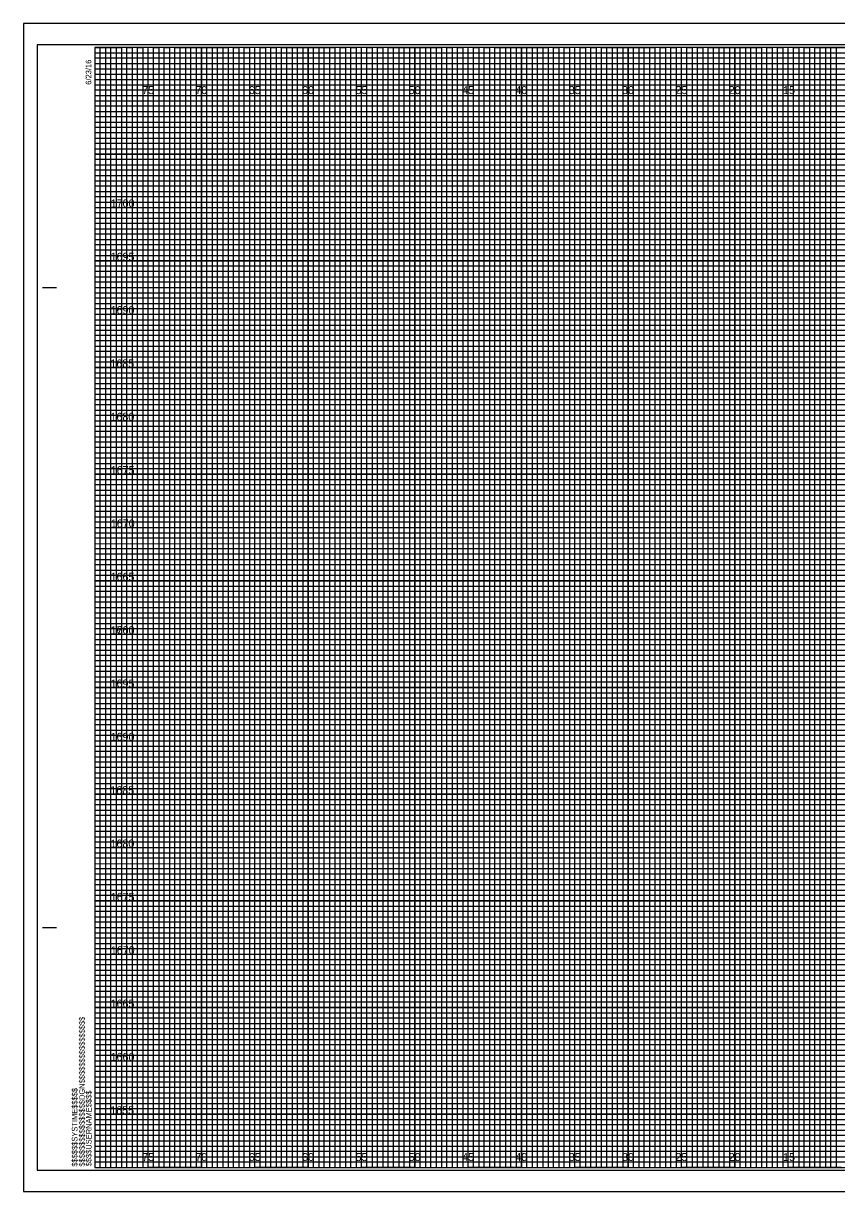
# Model space of a CAD drawing. Extents: x -7 to 162, y -2 to 217.
# Drawn here: x -6.7 to 69.5, y -2.3 to 107.3 of the extents above; entities that cross this region are included whole.
import ezdxf

# ---------------------------------------------------------------- set-up
doc = ezdxf.new("R2010")
doc.units = 0
for name, color, linetype in [('Raster_Level_0', 7, 'Continuous'), ('Scratch_Level_3', 7, 'Continuous'), ('Sheet Cross Section CELL', 7, 'Continuous'), ('Sheet Cross Section Grid Major CELL', 7, 'Continuous'), ('Sheet Cross Section Grid Middle CELL', 7, 'Continuous'), ('Sheet Cross Section Grid Minor 1 CELL', 7, 'Continuous'), ('Sheet Cross Section Grid Minor 2 CELL', 7, 'Continuous'), ('Sheet Cutting Line CELL', 7, 'Continuous'), ('Sheet DOT Grid CELL', 7, 'Continuous'), ('Sheet Plot Border Inside CELL', 7, 'Continuous'), ('Sheet Plot Border Outside CELL', 7, 'Continuous')]:
    doc.layers.add(name, color=color, linetype=linetype)

msp = doc.modelspace()

# ---------------------------------------------------------------- linework, layer by layer
at = {"layer": 'Sheet Cross Section CELL'}
for p, q in [((-4.9, 82.5), (-3.65, 82.5)), ((-4.85, 82.5), (-3.6, 82.5)), ((-4.9, 22.5), (-3.65, 22.5)), ((-4.85, 22.5), (-3.6, 22.5)), ((0, 0), (0, 0)), ((0, 0), (0, 0)), ((0, 0), (0, 0)), ((0, 0), (0, 0)), ((0, 0), (0, 0)), ((0, 0), (0, 0)), ((0, 0), (0, 0))]:
    msp.add_line(p, q, dxfattribs=at)
msp.add_lwpolyline([(160, 105), (0, 105), (0, 0), (160, 0)], close=True, dxfattribs=at)
at = {"layer": 'Sheet Cross Section Grid Major CELL'}
for p, q in [((5, 105), (0, 105)), ((5, 0), (5, 105)), ((15, 105), (10, 105)), ((10, 105), (10, 0)), ((15, 0), (15, 105)), ((25, 105), (20, 105)), ((20, 105), (20, 0)), ((25, 0), (25, 105)), ((35, 105), (30, 105)), ((30, 105), (30, 0)), ((35, 0), (35, 105)), ((45, 105), (40, 105)), ((40, 105), (40, 0)), ((45, 0), (45, 105)), ((55, 105), (50, 105)), ((50, 105), (50, 0)), ((55, 0), (55, 105)), ((65, 105), (60, 105)), ((60, 105), (60, 0)), ((65, 0), (65, 105)), ((10, 0), (5, 0)), ((20, 0), (15, 0)), ((30, 0), (25, 0)), ((40, 0), (35, 0)), ((50, 0), (45, 0)), ((60, 0), (55, 0)), ((70, 0), (65, 0))]:
    msp.add_line(p, q, dxfattribs=at)
for points in [[(0, 100), (160, 100), (160, 95), (0, 95)], [(0, 90), (160, 90), (160, 85), (0, 85)], [(0, 80), (160, 80), (160, 75), (0, 75)], [(0, 70), (160, 70), (160, 65), (0, 65)], [(0, 60), (160, 60), (160, 55), (0, 55)], [(0, 50), (160, 50), (160, 45), (0, 45)], [(0, 40), (160, 40), (160, 35), (0, 35)], [(0, 30), (160, 30), (160, 25), (0, 25)], [(0, 20), (160, 20), (160, 15), (0, 15)], [(0, 10), (160, 10), (160, 5), (0, 5)]]:
    msp.add_lwpolyline(points, dxfattribs=at)
at = {"layer": 'Sheet Cross Section Grid Middle CELL'}
for points in [[(0, 105), (2.5, 105), (2.5, 0), (7.5, 0), (7.5, 105), (12.5, 105), (12.5, 0), (17.5, 0), (17.5, 105), (22.5, 105), (22.5, 0), (27.5, 0), (27.5, 105), (32.5, 105), (32.5, 0), (37.5, 0), (37.5, 105), (42.5, 105), (42.5, 0), (47.5, 0), (47.5, 105), (52.5, 105), (52.5, 0), (57.5, 0), (57.5, 105), (62.5, 105), (62.5, 0), (67.5, 0), (67.5, 105), (72.5, 105)], [(0, 102.5), (137.5, 102.5)], [(0, 92.5), (160, 92.5), (160, 97.5), (0, 97.5)], [(0, 82.5), (160, 82.5), (160, 87.5), (0, 87.5)], [(0, 72.5), (160, 72.5), (160, 77.5), (0, 77.5)], [(0, 62.5), (160, 62.5), (160, 67.5), (0, 67.5)], [(0, 52.5), (160, 52.5), (160, 57.5), (0, 57.5)], [(0, 42.5), (160, 42.5), (160, 47.5), (0, 47.5)], [(0, 32.5), (160, 32.5), (160, 37.5), (0, 37.5)], [(0, 22.5), (160, 22.5), (160, 27.5), (0, 27.5)], [(0, 12.5), (160, 12.5), (160, 17.5), (0, 17.5)], [(0, 2.5), (160, 2.5), (160, 7.5), (0, 7.5)]]:
    msp.add_lwpolyline(points, dxfattribs=at)
at = {"layer": 'Sheet Cross Section Grid Minor 1 CELL'}
for p, q in [((0, 104.5), (130, 104.5)), ((130, 103.99), (0, 103.99)), ((0, 103.99), (0, 103.5)), ((0, 103.5), (130, 103.5)), ((130, 102.95), (0, 102.95)), ((0, 102.95), (0, 102)), ((0, 102), (160, 102))]:
    msp.add_line(p, q, dxfattribs=at)
for points in [[(0, 101.5), (135, 101.5), (160, 101.5), (160, 101), (0, 101)], [(0, 100.5), (160, 100.5), (160, 99.5), (0, 99.5)], [(0, 99), (160, 99), (160, 98.5), (0, 98.49)], [(0, 98), (160, 98), (160, 97), (0, 97)], [(0, 96.5), (160, 96.5), (160, 96), (0, 96)], [(0, 95.5), (160, 95.5), (160, 94.5), (0, 94.5)], [(0, 94), (160, 94), (160, 93.5), (0, 93.5)], [(0, 93), (160, 93), (160, 92), (0, 92)], [(0, 91.5), (160, 91.5), (160, 91), (0, 91)], [(0, 90.5), (160, 90.5), (160, 89.5), (0, 89.5)], [(0, 89), (160, 89), (160, 88.5), (0, 88.5)], [(0, 88), (160, 88), (160, 86.98), (160, 86.5), (160, 86), (0, 86)], [(0, 87), (160, 87), (160, 86.5), (0, 86.5)], [(0, 85.5), (160, 85.5), (160, 84.5), (0, 84.52)], [(0, 84.52), (160, 84.5), (160, 84), (0, 84)], [(0, 83.5), (160, 83.5), (160, 83), (0, 83)], [(0, 82), (160, 82), (160, 81.5), (0, 81.5)], [(0, 81), (160, 81), (160, 80.5), (0, 80.5)], [(-0.04, 79.45), (160, 79.45), (160, 78.94), (-0.04, 78.94)], [(0, 78.5), (160, 78.5), (160, 78), (0, 78)], [(0, 77), (160, 77), (160, 76.5), (0, 76.5)], [(0, 76), (160, 76), (160, 75.5), (0, 75.5)], [(0, 74.5), (160, 74.5), (160, 74), (0, 74)], [(0, 73.5), (160, 73.5), (160, 73), (0, 73)], [(0, 72), (160, 72), (160, 71.5), (0, 71.5)], [(0, 71), (160, 71), (160, 70.5), (0, 70.5)], [(0, 69.5), (160, 69.5), (160, 68.99), (0, 69)], [(0, 68.5), (160, 68.5), (160, 68), (0, 68)], [(0, 67), (160, 67), (160, 66.5), (0, 66.5)], [(0, 66), (160, 66), (160, 65.5), (0, 65.5)], [(0, 64.5), (160, 64.5), (160, 64), (0, 64)], [(0, 63.5), (160, 63.5), (160, 63), (0, 63)], [(0, 62), (160, 62), (160, 61.5), (0, 61.5)], [(0, 61), (160, 61), (160, 60.5), (0, 60.5)], [(0, 59.5), (160, 59.5), (160, 59), (0, 59)], [(0, 58.5), (160.03, 58.45), (160, 58), (0, 58)], [(0, 57), (160, 57), (160, 56.5), (0, 56.5)], [(0, 56), (160, 56), (160, 55.5), (0, 55.5)], [(0, 54.5), (160, 54.5), (160, 54), (0, 54)], [(0, 53.5), (160, 53.5), (160, 53), (0, 53)], [(0, 52), (160, 52), (160, 51.5), (0, 51.5)], [(0, 51), (160, 51), (160, 50.5), (0, 50.5)], [(0, 49.5), (160, 49.5), (160, 49), (0, 49)], [(0, 48.5), (160, 48.5), (160, 48), (0, 48)], [(0, 47), (160, 47), (160, 46.5), (0, 46.5)], [(0, 46), (160, 46), (160, 45.5), (0, 45.5)], [(0, 44.5), (160, 44.5), (160, 44), (0, 44)], [(0, 43.5), (160, 43.5), (160, 43), (0, 43)], [(0, 42), (160, 42), (160, 41.5), (0, 41.5)], [(0, 41), (160, 41), (160, 40.5), (0, 40.5)], [(0, 39.5), (160, 39.5), (160, 38.99), (0, 39)], [(0, 38.5), (160, 38.5), (160, 38), (0, 38)], [(0, 37), (160, 37), (160, 36.5), (0, 36.5)], [(0, 36), (160, 36), (160, 35.5), (0, 35.5)], [(0, 34.5), (160, 34.5), (160, 34), (0, 34)], [(0, 33.5), (160, 33.5), (160, 33), (0, 33)], [(0, 32), (160, 32), (160, 31.5), (0, 31.5)], [(0, 31), (160, 31), (160, 30.5), (0, 30.5)], [(0, 29.5), (160, 29.5), (160, 29), (0, 29)], [(0, 28.5), (160.03, 28.46), (160, 28), (0, 28)], [(0, 27), (160, 27), (160, 26.5), (0, 26.5)], [(0, 26), (160, 26), (160, 25.5), (0, 25.5)], [(0, 24.5), (160, 24.5), (160, 24), (0, 24)], [(0, 23.5), (160, 23.5), (160, 23), (0, 23)], [(0, 22), (160, 22), (160, 21.5), (0, 21.5)], [(0, 21), (160, 21), (160, 20.5), (0, 20.5)], [(0, 19.5), (160, 19.5), (160, 19), (0, 19)], [(0, 18.5), (160, 18.5), (160, 18), (0, 18)], [(0, 17), (160, 17), (160, 16.5), (0, 16.5)], [(0, 16), (160, 16), (160, 15.5), (0, 15.5)], [(0, 14.5), (160, 14.5), (160, 14), (0, 14)], [(0, 13.5), (160, 13.5), (160, 13), (0, 13)], [(0, 12), (160, 12), (160, 11.5), (0, 11.5)], [(0, 11), (160, 11), (160, 10.5), (0, 10.5)], [(0, 9.5), (160, 9.5), (160, 9), (0, 9)], [(0, 8.5), (160, 8.5), (160, 8), (0, 8)], [(0, 7), (160, 7), (160, 6.5), (0, 6.5)], [(0, 6), (160, 6), (160, 5.5), (0, 5.5)], [(0, 4.5), (160, 4.5), (160, 4), (0, 4)], [(0, 3.5), (160, 3.5), (160, 3), (0, 3)], [(0, 2), (160, 2), (160, 1.5), (0, 1.5)], [(0, 1), (160, 1), (160, 0.5), (0, 0.5)]]:
    msp.add_lwpolyline(points, dxfattribs=at)
at = {"layer": 'Sheet Cross Section Grid Minor 2 CELL'}
for points in [[(0, 0), (0.5, 0), (0.5, 105), (1, 105), (1, 0)], [(1, 0), (1.5, 0), (1.5, 105), (2, 105), (2, 0)], [(2.5, 0), (3, 0), (3, 105), (3.5, 105), (3.5, 0)], [(3.5, 0), (4, 0), (4, 105), (4.5, 105), (4.5, 0)], [(5, 0), (5.5, 0), (5.5, 105), (6, 105), (6, 0)], [(6, 0), (6.5, 0), (6.5, 105), (7, 105), (7, 0)], [(7.5, 0), (8, 0), (8, 105), (8.5, 105), (8.5, 0)], [(8.5, 0), (9, 0), (9, 105), (9.5, 105), (9.5, 0)], [(10, 0), (10.5, 0), (10.5, 105), (11, 105), (11, 0)], [(11, 0), (11.5, 0), (11.5, 105), (12, 105), (12, 0)], [(12.5, 0), (13, 0), (13, 105), (13.5, 105), (13.5, 0)], [(13.5, 0), (14, 0), (14, 105), (14.5, 105), (14.5, 0)], [(15, 0), (15.5, 0), (15.5, 105), (16, 105), (16, 0)], [(16, 0), (16.5, 0), (16.5, 105), (17, 105), (17, 0)], [(17.5, 0), (18, 0), (18, 105), (18.5, 105), (18.5, 0)], [(18.5, 0), (19, 0), (19, 105), (19.5, 105), (19.5, 0)], [(20, 0), (20.5, 0), (20.5, 105), (21, 105), (21, 0)], [(21, 0), (21.5, 0), (21.5, 105), (22, 105), (22, 0)], [(22.5, 0), (23, 0), (23, 105), (23.5, 105), (23.5, 0)], [(23.5, 0), (24, 0), (24, 105), (24.5, 105), (24.5, 0)], [(25, 0), (25.5, 0), (25.5, 105), (26, 105), (26, 0)], [(26, 0), (26.5, 0), (26.5, 105), (27, 105), (27, 0)], [(27.5, 0), (28, 0), (28, 105), (28.5, 105), (28.5, 0)], [(28.5, 0), (29, 0), (29, 105), (29.5, 105), (29.5, 0)], [(30, 0), (30.5, 0), (30.5, 105), (31, 105), (31, 0)], [(31, 0), (31.5, 0), (31.5, 105), (32, 105), (32, 0)], [(32.5, 0), (33, 0), (33, 105), (33.5, 105), (33.5, 0)], [(33.5, 0), (34, 0), (34, 105), (34.5, 105), (34.5, 0)], [(35, 0), (35.5, 0), (35.5, 105), (36, 105), (36, 0)], [(36, 0), (36.5, 0), (36.5, 105), (37, 105), (37, 0)], [(37.5, 0), (38, 0), (38, 105), (38.5, 105), (38.5, 0)], [(38.5, 0), (39, 0), (39, 105), (39.5, 105), (39.5, 0)], [(40, 0), (40.5, 0), (40.5, 105), (41, 105), (41, 0)], [(41, 0), (41.5, 0), (41.5, 105), (42, 105), (42, 0)], [(42.5, 0), (43, 0), (43, 105), (43.5, 105), (43.5, 0)], [(43.5, 0), (44, 0), (44, 105), (44.5, 105), (44.5, 0)], [(45, 0), (45.5, 0), (45.5, 105), (46, 105), (46, 0)], [(46, 0), (46.5, 0), (46.5, 105), (47, 105), (47, 0)], [(47.5, 0), (48, 0), (48, 105), (48.5, 105), (48.5, 0)], [(48.5, 0), (49, 0), (49, 105), (49.5, 105), (49.5, 0)], [(50, 0), (50.5, 0), (50.5, 105), (51, 105), (51, 0)], [(51, 0), (51.5, 0), (51.5, 105), (52, 105), (52, 0)], [(52.5, 0), (53, 0), (53, 105), (53.5, 105), (53.5, 0)], [(53.5, 0), (54, 0), (54, 105), (54.5, 105), (54.5, 0)], [(55, 0), (55.5, 0), (55.5, 105), (56, 105), (56, 0)], [(56, 0), (56.5, 0), (56.5, 105), (57, 105), (57, 0)], [(57.5, 0), (58, 0), (58, 105), (58.5, 105), (58.5, 0)], [(58.5, 0), (59, 0), (59, 105), (59.5, 105), (59.5, 0)], [(60, 0), (60.5, 0), (60.5, 105), (61, 105), (61, 0)], [(61, 0), (61.5, 0), (61.5, 105), (62, 105), (62, 0)], [(62.5, 0), (63, 0), (63, 105), (63.5, 105), (63.5, 0)], [(63.5, 0), (64, 0), (64, 105), (64.5, 105), (64.5, 0)], [(65, 0), (65.5, 0), (65.5, 105), (66, 105), (66, 0)], [(66, 0), (66.5, 0), (66.5, 105), (67, 105), (67, 0)], [(67.5, 0), (68, 0), (68, 105), (68.5, 105), (68.5, 0)], [(68.5, 0), (69, 0), (69, 105), (69.5, 105), (69.5, 0)]]:
    msp.add_lwpolyline(points, dxfattribs=at)
at = {"layer": 'Sheet Cutting Line CELL'}
for p, q in [((161.65, 107.25), (-6.7, 107.25)), ((-6.7, 107.25), (-6.7, -2.25)), ((-6.7, -2.25), (161.65, -2.25))]:
    msp.add_line(p, q, dxfattribs=at)
at = {"layer": 'Sheet DOT Grid CELL'}
for p, q in [((5, 0), (5, 105)), ((10, 0), (10, 105)), ((15, 0), (15, 105)), ((20, 0), (20, 105)), ((25, 0), (25, 105)), ((30, 0), (30, 105)), ((35, 0), (35, 105)), ((40, 0), (40, 105)), ((45, 0), (45, 105)), ((50, 0), (50, 105)), ((55, 0), (55, 105)), ((60, 0), (60, 105)), ((65, 0), (65, 105)), ((0, 100), (160, 100)), ((0, 95), (160, 95)), ((0, 90), (160, 90)), ((0, 85), (160, 85)), ((0, 80), (160, 80)), ((0, 75), (160, 75)), ((0, 70), (160, 70)), ((0, 65), (160, 65)), ((0, 60), (160, 60)), ((0, 55), (160, 55)), ((0, 50), (160, 50)), ((0, 45), (160, 45)), ((0, 40), (160, 40)), ((0, 35), (160, 35)), ((0, 30), (160, 30)), ((0, 25), (160, 25)), ((0, 20), (160, 20)), ((0, 15), (160, 15)), ((0, 10), (160, 10)), ((0, 5), (160, 5))]:
    msp.add_line(p, q, dxfattribs=at)
at = {"layer": 'Sheet Plot Border Inside CELL'}
msp.add_lwpolyline([(-5.4, -0.25), (161.2, -0.25), (161.2, 105.25), (-5.4, 105.25)], close=True, dxfattribs=at)
at = {"layer": 'Sheet Plot Border Outside CELL'}
msp.add_lwpolyline([(-6.7, -2.25), (161.65, -2.25), (161.65, 107.25), (-6.7, 107.25)], close=True, dxfattribs=at)

# ---------------------------------------------------------------- texts
at = {"layer": 'Raster_Level_0'}
for s, p in [('75', (4.44, 100.62)), ('70', (9.43, 100.62)), ('65', (14.44, 100.62)), ('60', (19.43, 100.62)), ('55', (24.44, 100.62)), ('50', (29.43, 100.62)), ('45', (34.44, 100.62)), ('40', (39.43, 100.62)), ('35', (44.44, 100.62)), ('30', (49.43, 100.62)), ('25', (54.44, 100.62)), ('20', (59.43, 100.62)), ('15', (64.53, 100.62)), ('75', (4.44, 0.62)), ('70', (9.43, 0.62)), ('65', (14.44, 0.62)), ('60', (19.43, 0.62)), ('55', (24.44, 0.62)), ('50', (29.43, 0.62)), ('45', (34.44, 0.62)), ('40', (39.43, 0.62)), ('35', (44.44, 0.62)), ('30', (49.43, 0.62)), ('25', (54.44, 0.62)), ('20', (59.43, 0.62)), ('15', (64.53, 0.62))]:
    msp.add_text(s, height=0.75, dxfattribs=at).set_placement(p)
at = {"layer": 'Scratch_Level_3'}
for s, p in [('1700', (1.49, 90)), ('1695', (1.48, 85)), ('1690', (1.48, 80)), ('1685', (1.46, 75)), ('1680', (1.47, 70)), ('1675', (1.49, 65)), ('1670', (1.5, 60)), ('1665', (1.48, 55)), ('1660', (1.48, 50)), ('1700', (1.49, 50)), ('1695', (1.48, 45)), ('1690', (1.48, 40)), ('1685', (1.46, 35)), ('1680', (1.47, 30)), ('1675', (1.49, 25)), ('1670', (1.5, 20)), ('1665', (1.48, 15)), ('1660', (1.48, 10)), ('1655', (1.45, 5))]:
    msp.add_text(s, height=0.75, dxfattribs=at).set_placement(p)
at = {"layer": 'Sheet Cross Section CELL'}
for s, p in [('6/23/16', (-0.33, 101.5)), ('$$$$$$$$$$$$$$$$DGN$$$$$$$$$$$$$$$$', (-0.94, 0.09)), ('$$$$$$SYSTIME$$$$$', (-1.63, 0.09)), ('$$$$USERNAME$$$$', (-0.31, 0.12))]:
    msp.add_text(s, height=0.525, rotation=90, dxfattribs=at).set_placement(p)

doc.saveas('drawing.dxf')
